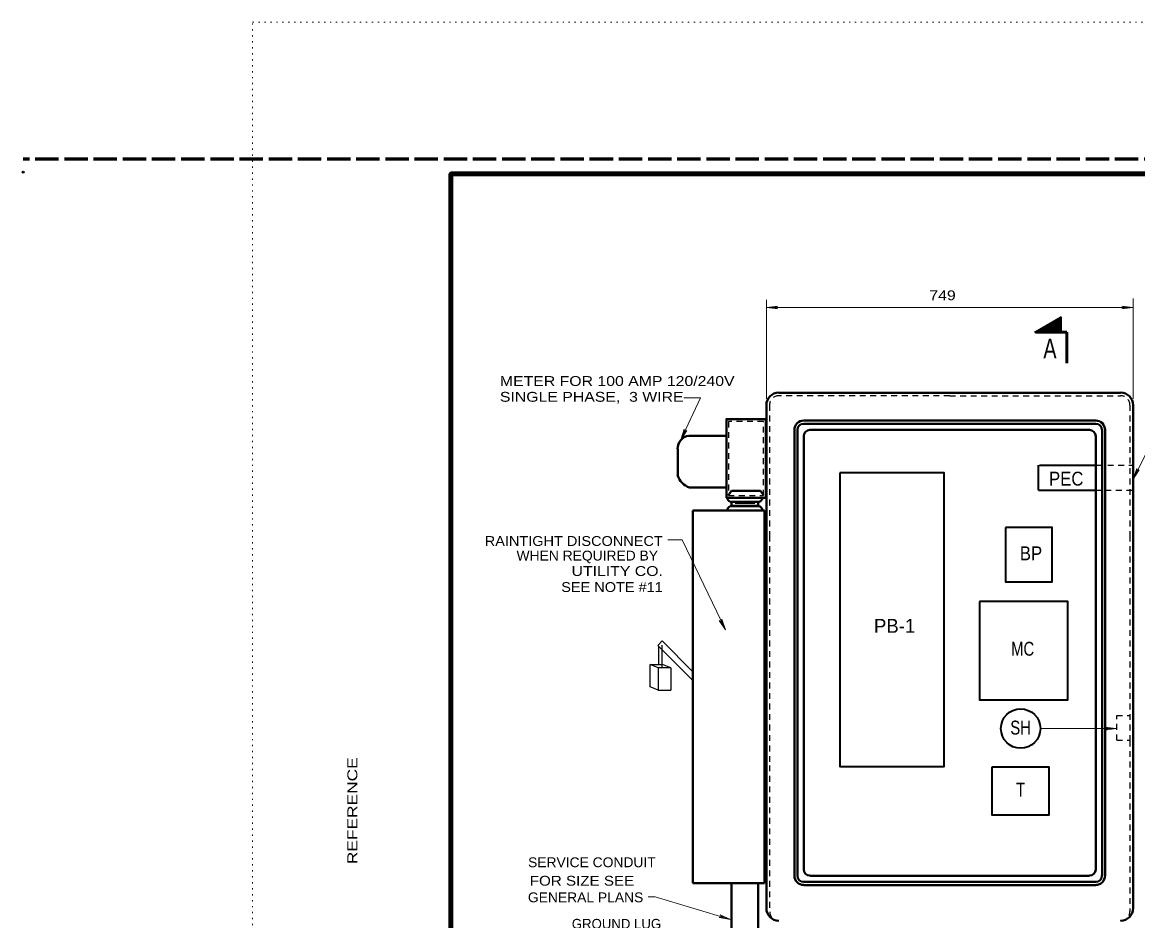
# Model space of a CAD drawing. Extents: x 312583 to 312854, y 144419 to 144597.
# Drawn here: x 312583.5 to 312669.5, y 144527.5 to 144596.8 of the extents above; entities that cross this region are included whole.
import ezdxf
from ezdxf.enums import TextEntityAlignment as Align

# ---------------------------------------------------------------- set-up
doc = ezdxf.new("R2010")
doc.units = 0
doc.header["$LTSCALE"] = 0.3
doc.header["$PDMODE"] = 32
doc.header["$PDSIZE"] = 0.15
for name, pattern in [('DOTTED', [1.5, 0.3, -1.2]), ('LONG_DASHED', [7.5, 6, -1.5]), ('SHORT_DASHED', [2.7, 1.5, -1.2])]:
    doc.linetypes.add(name, pattern=pattern)
for name, color, linetype, lineweight in [('1', 7, 'Continuous', 25), ('2', 7, 'Continuous', 13), ('63', 7, 'DOTTED', 13)]:
    doc.layers.add(name, color=color, linetype=linetype, lineweight=lineweight)

msp = doc.modelspace()

# ---------------------------------------------------------------- linework, layer by layer
at = {"layer": '1', "linetype": 'LONG_DASHED', "lineweight": 60}
msp.add_line((312851.75, 144586.2246), (312583.526, 144586.2246), dxfattribs=at)
at = {"layer": '1', "lineweight": 35}
for p, q in [((312663.2731, 144572.887), (312662.8515, 144573.6154)), ((312663.3038, 144572.887), (312662.8745, 144573.6307)), ((312663.3268, 144572.8947), (312662.8975, 144573.6384)), ((312663.3575, 144572.8947), (312662.9128, 144573.6537)), ((312663.3805, 144572.887), (312662.9358, 144573.6614)), ((312663.4111, 144572.887), (312662.9588, 144573.6767)), ((312663.4341, 144572.887), (312662.9741, 144573.6844)), ((312663.4648, 144572.887), (312662.9971, 144573.6997)), ((312663.4955, 144572.887), (312663.0201, 144573.7074)), ((312663.5108, 144572.91), (312663.0355, 144573.7227)), ((312663.5108, 144572.9637), (312663.0661, 144573.7304)), ((312663.5108, 144573.002), (312663.0815, 144573.7457)), ((312663.5108, 144573.0557), (312663.1045, 144573.7534)), ((312663.5108, 144573.1017), (312663.1275, 144573.7687)), ((312663.5108, 144573.1477), (312663.1428, 144573.784)), ((312663.5108, 144573.1937), (312663.1658, 144573.7917)), ((312663.5108, 144573.2474), (312663.1888, 144573.807)), ((312663.5108, 144573.2934), (312663.2041, 144573.8224)), ((312663.5108, 144573.3394), (312663.2271, 144573.83)), ((312663.5108, 144573.393), (312663.2425, 144573.8454)), ((312663.5108, 144573.439), (312663.2655, 144573.853)), ((312663.5108, 144573.485), (312663.2885, 144573.8684)), ((312663.5108, 144573.5387), (312663.3038, 144573.876)), ((312663.5108, 144573.5847), (312663.3345, 144573.8914)), ((312663.5108, 144573.6307), (312663.3498, 144573.899)), ((312663.5108, 144573.6767), (312663.3728, 144573.9144)), ((312663.5108, 144573.7304), (312663.3958, 144573.922)), ((312663.5108, 144573.7687), (312663.4111, 144573.9374)), ((312663.5108, 144573.8224), (312663.4341, 144573.945)), ((312663.5108, 144573.8684), (312663.4571, 144573.9604)), ((312663.5108, 144573.922), (312663.4725, 144573.9757)), ((312663.5108, 144573.968), (312663.4955, 144573.9834)), ((312661.6095, 144572.887), (312661.6095, 144572.9024)), ((312661.6401, 144572.887), (312661.6325, 144572.91)), ((312661.6708, 144572.887), (312661.6478, 144572.9254)), ((312661.6938, 144572.887), (312661.6708, 144572.933)), ((312661.7245, 144572.887), (312661.6938, 144572.9484)), ((312661.7475, 144572.887), (312661.7091, 144572.956)), ((312661.7781, 144572.887), (312661.7321, 144572.9714)), ((312661.8088, 144572.887), (312661.7551, 144572.979)), ((312661.8395, 144572.887), (312661.7705, 144572.9944)), ((312661.8625, 144572.887), (312661.7935, 144573.002)), ((312661.8855, 144572.887), (312661.8165, 144573.0174)), ((312661.9161, 144572.887), (312661.8395, 144573.025)), ((312661.9391, 144572.887), (312661.8548, 144573.0404)), ((312661.9698, 144572.887), (312661.8778, 144573.0557)), ((312662.0005, 144572.887), (312661.9008, 144573.0634)), ((312662.0311, 144572.887), (312661.9161, 144573.0787)), ((312662.0541, 144572.887), (312661.9391, 144573.094)), ((312662.0848, 144572.887), (312661.9621, 144573.1017)), ((312662.1078, 144572.887), (312661.9775, 144573.117)), ((312662.1385, 144572.887), (312662.0005, 144573.1247)), ((312662.1691, 144572.887), (312662.0235, 144573.14)), ((312662.1921, 144572.887), (312662.0388, 144573.1477)), ((312662.2228, 144572.887), (312662.0695, 144573.163)), ((312662.2458, 144572.887), (312662.0848, 144573.1707)), ((312662.2765, 144572.887), (312662.1078, 144573.186)), ((312662.3071, 144572.887), (312662.1308, 144573.1937)), ((312662.3301, 144572.887), (312662.1461, 144573.209)), ((312662.3608, 144572.887), (312662.1691, 144573.2167)), ((312662.3838, 144572.887), (312662.1921, 144573.232)), ((312662.4145, 144572.887), (312662.2075, 144573.2474)), ((312662.4375, 144572.887), (312662.2305, 144573.255)), ((312662.4681, 144572.887), (312662.2535, 144573.2704)), ((312662.4988, 144572.887), (312662.2688, 144573.2857)), ((312662.5295, 144572.887), (312662.2918, 144573.2934)), ((312662.5525, 144572.887), (312662.3148, 144573.3087)), ((312662.5755, 144572.887), (312662.3378, 144573.3164)), ((312662.6061, 144572.887), (312662.3531, 144573.3317)), ((312662.6368, 144572.887), (312662.3761, 144573.3394)), ((312662.6598, 144572.887), (312662.3991, 144573.3547)), ((312662.6905, 144572.887), (312662.4145, 144573.3624)), ((312662.7211, 144572.887), (312662.4375, 144573.3777)), ((312662.7441, 144572.887), (312662.4605, 144573.3854)), ((312662.7748, 144572.887), (312662.4758, 144573.4007)), ((312662.8055, 144572.887), (312662.4988, 144573.4084)), ((312662.8285, 144572.887), (312662.5218, 144573.4237)), ((312662.8591, 144572.8947), (312662.5371, 144573.439)), ((312662.8821, 144572.887), (312662.5678, 144573.4467)), ((312662.9128, 144572.887), (312662.5831, 144573.462)), ((312662.9358, 144572.887), (312662.6061, 144573.4697)), ((312662.9665, 144572.887), (312662.6291, 144573.485)), ((312662.9971, 144572.887), (312662.6445, 144573.4927)), ((312663.0278, 144572.887), (312662.6675, 144573.508)), ((312663.0508, 144572.887), (312662.6905, 144573.5157)), ((312663.0738, 144572.887), (312662.7058, 144573.531)), ((312663.1045, 144572.8947), (312662.7288, 144573.5387)), ((312663.1351, 144572.887), (312662.7518, 144573.554)), ((312663.1581, 144572.887), (312662.7671, 144573.5617)), ((312663.1888, 144572.887), (312662.7901, 144573.577)), ((312663.2195, 144572.887), (312662.8131, 144573.5924)), ((312663.2425, 144572.887), (312662.8361, 144573.6)), ((312661.8088, 144560.7047), (312661.8088, 144562.6214)), ((312661.8778, 144562.6214), (312666.3398, 144562.6214)), ((312661.8088, 144560.7047), (312666.1635, 144560.7047))]:
    msp.add_line(p, q, dxfattribs=at)
at = {"layer": '1', "lineweight": 53}
for p in [(312663.5108, 144572.887), (312663.9861, 144570.495)]:
    msp.add_line(p, (312663.9861, 144572.887), dxfattribs=at)
at = {"layer": '1', "lineweight": 40}
for p, q in [((312654.9625, 144568.218), (312641.7911, 144568.218)), ((312654.9625, 144568.218), (312668.1415, 144568.218)), ((312640.8328, 144567.2597), (312640.8328, 144528.451)), ((312669.0998, 144567.2597), (312669.0998, 144528.451)), ((312654.9625, 144566.0637), (312643.7078, 144566.0637)), ((312654.9625, 144566.0637), (312666.2248, 144566.0637)), ((312642.9871, 144565.435), (312642.9871, 144530.9657)), ((312642.9871, 144565.343), (312642.9871, 144557.201)), ((312643.2248, 144530.9657), (312643.2248, 144565.343)), ((312654.9625, 144565.826), (312643.7078, 144565.826)), ((312654.9625, 144565.343), (312644.1831, 144565.343)), ((312654.9625, 144565.826), (312666.2248, 144565.826)), ((312654.9625, 144565.343), (312665.7495, 144565.343)), ((312666.7078, 144565.343), (312666.7078, 144530.9657)), ((312666.9455, 144565.343), (312666.9455, 144557.201)), ((312637.7431, 144564.8984), (312634.8451, 144564.8984)), ((312643.7078, 144564.8677), (312643.7078, 144531.4487)), ((312666.2248, 144564.8677), (312666.2248, 144531.4487)), ((312633.9865, 144561.8547), (312633.9865, 144563.894)), ((312637.7431, 144560.904), (312634.8988, 144560.904)), ((312638.1265, 144560.6434), (312637.8888, 144560.2907)), ((312638.1265, 144560.6434), (312640.3728, 144560.6434)), ((312640.3728, 144560.6434), (312640.6028, 144560.306)), ((312635.1518, 144559.1407), (312635.1518, 144530.383)), ((312635.1518, 144559.1407), (312640.6795, 144559.1407)), ((312638.0345, 144559.8), (312640.2808, 144559.8)), ((312638.0345, 144559.455), (312640.2808, 144559.455)), ((312638.1265, 144559.8), (312638.1265, 144559.455)), ((312638.6861, 144559.1407), (312640.2425, 144559.1407)), ((312640.1811, 144559.8), (312640.1811, 144559.455)), ((312640.6795, 144559.1407), (312640.6795, 144530.383)), ((312642.9871, 144557.201), (312642.9871, 144539.468)), ((312654.9625, 144530.9657), (312644.1831, 144530.9657)), ((312654.9625, 144530.9657), (312665.7495, 144530.9657)), ((312635.1518, 144530.383), (312640.6795, 144530.383)), ((312638.1265, 144521.597), (312638.1265, 144530.383)), ((312640.1811, 144521.5817), (312640.1811, 144530.383)), ((312654.9625, 144530.4904), (312643.7078, 144530.4904)), ((312654.9625, 144530.245), (312643.7078, 144530.245)), ((312654.9625, 144530.4904), (312666.2248, 144530.4904)), ((312654.9625, 144530.245), (312666.2248, 144530.245))]:
    msp.add_line(p, q, dxfattribs=at)
at = {"layer": '1', "linetype": 'SHORT_DASHED'}
for p, q in [((312654.9625, 144567.9804), (312641.7911, 144567.9804)), ((312654.9625, 144567.9804), (312668.1415, 144567.9804)), ((312641.0705, 144567.2597), (312641.0705, 144557.201)), ((312668.8621, 144567.2597), (312668.8621, 144557.201)), ((312666.3398, 144562.6214), (312669.1765, 144562.6214)), ((312666.1635, 144560.7047), (312669.1765, 144560.7047)), ((312667.8501, 144543.332), (312668.8621, 144543.332)), ((312667.8501, 144541.4154), (312667.8501, 144543.332)), ((312667.8501, 144541.4154), (312668.8621, 144541.4154))]:
    msp.add_line(p, q, dxfattribs=at)
at = {"layer": '1'}
for p, q in [((312635.1518, 144546.023), (312632.4455, 144548.7217)), ((312632.5068, 144548.668), (312632.5068, 144547.196)), ((312632.7751, 144548.7447), (312632.7751, 144547.0657)), ((312633.4498, 144546.9967), (312632.4915, 144546.9967)), ((312633.4498, 144546.9967), (312633.4498, 144545.264))]:
    msp.add_line(p, q, dxfattribs=at)
at = {"layer": '1', "lineweight": 158}
msp.add_lwpolyline([(312616.5, 144423.1446), (312616.5, 144585.0846), (312849, 144585.0846)], dxfattribs=at)
at = {"layer": '1', "lineweight": 53}
msp.add_lwpolyline([(312663.5108, 144572.887), (312663.5108, 144573.9987), (312661.5941, 144572.887)], close=True, dxfattribs=at)
at = {"layer": '1', "lineweight": 40}
msp.add_lwpolyline([(312637.7431, 144560.099), (312637.7431, 144566.1787), (312640.7791, 144566.1787), (312640.7791, 144560.099)], close=True, dxfattribs=at)
at = {"layer": '1', "linetype": 'SHORT_DASHED'}
msp.add_lwpolyline([(312637.9041, 144565.987), (312637.9041, 144560.283), (312640.6028, 144560.283), (312640.6028, 144565.987)], close=True, dxfattribs=at)
at = {"layer": '1', "lineweight": 35}
for points in [[(312646.4985, 144562.0234), (312646.4985, 144539.3837), (312654.5485, 144539.3837), (312654.5485, 144562.0234)], [(312659.2558, 144557.822), (312659.2558, 144553.6207), (312662.8745, 144553.6207), (312662.8745, 144557.822)], [(312657.2701, 144552.1027), (312657.2701, 144544.5204), (312664.0781, 144544.5204), (312664.0781, 144552.1027)], [(312658.2055, 144539.3454), (312658.2055, 144535.65), (312662.6445, 144535.65), (312662.6445, 144539.3454)]]:
    msp.add_lwpolyline(points, close=True, dxfattribs=at)
at = {"layer": '1', "linetype": 'SHORT_DASHED'}
for points in [[(312641.0705, 144557.201), (312641.0705, 144539.468), (312641.0705, 144528.1674)], [(312668.8621, 144557.201), (312668.8621, 144541.3847), (312668.8621, 144528.2134)]]:
    msp.add_lwpolyline(points, dxfattribs=at)
at = {"layer": '1', "lineweight": 40}
msp.add_lwpolyline([(312666.9455, 144557.201), (312666.9455, 144539.468), (312666.9455, 144530.9657)], dxfattribs=at)
at = {"layer": '1'}
for points in [[(312635.1518, 144546.6977), (312632.7828, 144549.0667), (312632.4455, 144548.7217)], [(312632.4915, 144546.9967), (312632.4915, 144545.264), (312633.4498, 144545.264)]]:
    msp.add_lwpolyline(points, dxfattribs=at)
at = {"layer": '1', "lineweight": 40}
for centre, radius, start, end in [((312641.7873, 144567.2635), 0.9583, 90, 180), ((312668.1415, 144567.2635), 0.9583, 0, 90), ((312643.704, 144565.3469), 0.7188, 90, 180), ((312666.2248, 144565.3469), 0.7188, 0, 90), ((312643.704, 144565.3469), 0.4792, 90, 180), ((312644.1831, 144564.8677), 0.4792, 90, 180), ((312665.7456, 144564.8677), 0.4792, 0, 90), ((312666.2248, 144565.3469), 0.4792, 0, 90), ((312634.981, 144563.9124), 0.9986, 98.04414, 181.22047), ((312635.335, 144562.2424), 1.4076, 196.1071, 252.07041), ((312638.1522, 144560.1172), 0.3363, 181.13369, 249.16122), ((312640.1372, 144560.1694), 0.3943, 291.65866, 351.41461), ((312638.1522, 144559.1379), 0.3363, 110.83877, 178.86631), ((312640.1372, 144559.0857), 0.3943, 8.58539, 68.34134), ((312643.704, 144530.9667), 0.7188, 180, 270), ((312643.704, 144530.9667), 0.4792, 180, 270), ((312644.1831, 144531.4458), 0.4792, 180, 270), ((312665.7456, 144531.4458), 0.4792, 270, 0), ((312666.2248, 144530.9667), 0.7188, 270, 0), ((312666.2248, 144530.9667), 0.4792, 270, 0), ((312641.7873, 144528.451), 0.9583, 180, 270), ((312668.1415, 144528.451), 0.9583, 270, 0)]:
    msp.add_arc(centre, radius, start, end, dxfattribs=at)
at = {"layer": '1', "linetype": 'SHORT_DASHED'}
for centre, start, end in [((312641.7873, 144567.2635), 90, 180), ((312668.1415, 144567.2635), 0, 90), ((312641.8074, 144528.1702), 180, 233.89913), ((312668.1415, 144528.2115), 270, 0)]:
    msp.add_arc(centre, 0.7188, start, end, dxfattribs=at)
at = {"layer": '1'}
msp.add_point((312583.526, 144585.2246), dxfattribs=at)
at = {"layer": '2'}
for p, q in [((312640.8328, 144567.7427), (312640.8328, 144575.3787)), ((312669.0998, 144567.7427), (312669.0998, 144575.4784)), ((312640.8328, 144574.7884), (312641.6991, 144574.8957)), ((312640.8328, 144574.7884), (312669.0998, 144574.7884)), ((312640.8328, 144574.7884), (312641.6991, 144574.681)), ((312641.6991, 144574.8957), (312641.4231, 144574.7884)), ((312641.6991, 144574.681), (312641.4231, 144574.7884)), ((312668.2335, 144574.8957), (312668.5095, 144574.7884)), ((312669.0998, 144574.7884), (312668.2335, 144574.8957)), ((312668.2335, 144574.681), (312668.5095, 144574.7884)), ((312669.0998, 144574.7884), (312668.2335, 144574.681)), ((312635.7501, 144567.808), (312634.2241, 144564.5687)), ((312634.4544, 144567.808), (312635.7501, 144567.808)), ((312634.2241, 144564.5687), (312634.4974, 144565.395)), ((312634.2241, 144564.5687), (312634.6928, 144565.2986)), ((312634.4974, 144565.395), (312634.4791, 144565.0997)), ((312634.6928, 144565.2986), (312634.4791, 144565.0997)), ((312669.0998, 144561.548), (312669.3988, 144562.3684)), ((312669.0998, 144561.548), (312669.5828, 144562.2687)), ((312669.3988, 144562.3684), (312669.3681, 144562.0694)), ((312669.5828, 144562.2687), (312669.3681, 144562.0694)), ((312638.2338, 144559.5317), (312640.1121, 144559.5317)), ((312638.4331, 144559.6697), (312639.9435, 144559.6697)), ((312633.2248, 144556.8743), (312634.3427, 144556.8743)), ((312634.3427, 144556.8743), (312637.6665, 144549.9254)), ((312637.1933, 144550.6545), (312637.4118, 144550.458)), ((312637.6665, 144549.9254), (312637.1933, 144550.6545)), ((312637.3892, 144550.753), (312637.4118, 144550.458)), ((312637.6665, 144549.9254), (312637.3892, 144550.753)), ((312661.9545, 144542.3047), (312667.7888, 144542.3047)), ((312666.9225, 144542.412), (312667.1985, 144542.3047)), ((312667.7888, 144542.3047), (312666.9225, 144542.412)), ((312666.9225, 144542.1974), (312667.1985, 144542.3047)), ((312667.7888, 144542.3047), (312666.9225, 144542.1974)), ((312631.7145, 144529.3404), (312632.2615, 144529.3404)), ((312632.2615, 144529.3404), (312638.0575, 144527.5924)), ((312637.1988, 144527.738), (312637.4901, 144527.761)), ((312638.0575, 144527.5924), (312637.1988, 144527.738)), ((312637.2601, 144527.9374), (312637.4901, 144527.761)), ((312638.0575, 144527.5924), (312637.2601, 144527.9374))]:
    msp.add_line(p, q, dxfattribs=at)
at = {"layer": '2', "lineweight": 25}
for p, q in [((312632.4915, 144546.9967), (312631.8705, 144547.265)), ((312633.4498, 144546.9967), (312632.8288, 144547.265))]:
    msp.add_line(p, q, dxfattribs=at)
at = {"layer": '2'}
msp.add_lwpolyline([(312669.0998, 144561.548), (312674.7348, 144572.703), (312676.7588, 144572.703)], dxfattribs=at)
at = {"layer": '2', "lineweight": 25}
msp.add_lwpolyline([(312632.4915, 144545.264), (312631.8705, 144545.54), (312631.8705, 144547.265), (312632.8288, 144547.265)], dxfattribs=at)
at = {"layer": '2', "lineweight": 35}
msp.add_circle((312660.435, 144542.3109), 1.52, dxfattribs=at)
at = {"layer": '63'}
for p, q in [((312601.2, 144596.7846), (312853.5, 144596.7846)), ((312601.2, 144418.5846), (312601.2, 144596.7846))]:
    msp.add_line(p, q, dxfattribs=at)

# ---------------------------------------------------------------- texts
at = {"layer": '1', "width": 0.75}
msp.add_text('A', height=1.533, dxfattribs=at).set_placement((312662.6943, 144570.8554), align=Align.CENTER)
at = {"layer": '1', "width": 1.3}
msp.add_text('REFERENCE                                                              ', height=0.7682, rotation=90, dxfattribs=at).set_placement((312609.2854, 144531.8549))
at = {"layer": '2'}
for s, width, p in [('749 ', 1.2, (312653.3933, 144575.3489)), ('METER FOR 100 AMP 120/240V', 1.2, (312620.2781, 144568.7381)), ('SINGLE PHASE,  3 WIRE', 1.2, (312620.2781, 144567.5181)), ('RAINTIGHT DISCONNECT', 1.1, (312619.1116, 144556.3971)), ('WHEN REQUIRED BY', 1.05, (312621.5633, 144555.2706)), ('UTILITY CO.', 1.2, (312625.8018, 144554.0823)), ('SEE NOTE #11', 1.1, (312625.0102, 144552.845)), ('SERVICE CONDUIT', 1.05, (312622.4514, 144531.6177)), ('FOR SIZE SEE', 1.15, (312622.5832, 144530.1928)), ('GENERAL PLANS', 1.05, (312622.441, 144528.9136))]:
    msp.add_text(s, height=0.76, dxfattribs=dict(at, width=width)).set_placement(p)
for s, width, p in [('PEC', 0.9, (312663.9477, 144561.0497)), ('BP', 0.9, (312661.2338, 144555.292)), ('MC', 0.8, (312660.5897, 144547.932)), ('SH', 0.8, (312660.4326, 144541.8524)), ('T', 0.8, (312660.4326, 144537.0607))]:
    msp.add_text(s, height=1.072, dxfattribs=dict(at, width=width)).set_placement(p, align=Align.CENTER)
msp.add_text('PB-1', height=1.072, dxfattribs=at).set_placement((312650.7151, 144549.6954), align=Align.CENTER)
msp.add_text('GROUND LUG', height=0.76, dxfattribs=at).set_placement((312625.8243, 144526.8708))

doc.saveas('drawing.dxf')
